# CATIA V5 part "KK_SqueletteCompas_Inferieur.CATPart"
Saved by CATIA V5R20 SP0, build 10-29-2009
Part number: Squelette_compas_inferieur
Bounding box of the stored display mesh (mm): x -200 to 200, y 1056 to 1632, z -3072 to -2292
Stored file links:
  G:\Khaled_CFAO_2011\ST2M\ST2M_GR2\aboulegue\Khaled\CAD_thinkMOTION\KK_SqueletteCompas_Inferieur.CATPart
  G:\Khaled_CFAO_2011\ST2M\ST2M_GR2\aboulegue\Khaled\CAD_thinkMOTION\KK_Train_Atterrissage.CATProduct
  G:\Khaled_CFAO_2011\ST2M\ST2M_GR2\aboulegue\Khaled\CAD_thinkMOTION\KK_Squelette_TigeAmortisseur.CATPart
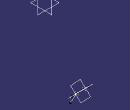
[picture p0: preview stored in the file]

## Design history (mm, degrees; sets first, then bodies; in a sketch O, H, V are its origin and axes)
Set1
  Point1: linked copy from another document
  Point2: linked copy from another document
  Plane1 "Plan reference": linked copy from another document
  Line1: linked copy from another document
Set2 "Set squelette compas inferieur"
  Line2: type PtPt, FirstPoint Point1, SecondPoint Point2
  Line3: type Normal, RefPoint Point2, RefSkin Plane1, Start -200, End 200
  Line4: type Normal, RefPoint Point1, RefSkin Plane1, Start -200, End 200
  Plane2 "Plan compas inferieur 1": type 2Lines, Element1 Line2, Element2 Line1
  Plane3 "Plan compas inferieur 2": type 2Lines, Element1 Line2, Element2 Line3
Body1 (main body)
